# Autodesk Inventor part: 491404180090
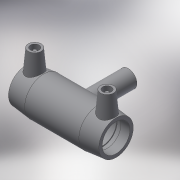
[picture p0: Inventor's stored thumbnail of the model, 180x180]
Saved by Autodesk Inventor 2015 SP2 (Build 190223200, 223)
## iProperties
Created: 2017-06
Part Number: 491404180090
Material: Generic
Description: PLASSON REDUCING TEE 180x90x180
Document SubType Name: Modeling
Designer: KIM
Mass: 57.3761 g
Surface Area: 241.06 cm^2
Volume: 57.3761 cm^3
Density: 1 g/cm^3
Appearance: Default
Author: KIM
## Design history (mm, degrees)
derived "491404.ipt"
feature "Solid1::491404.ipt"
tag "TaggingFeature1"
body "Solid1"
other parameters: "d0" = 422, "d2" = 245, "d3" = 106, "d4" = 84.4, "d5" = 220.5, "d6" = 171, "d8" = 168 deg, "d10" = 42.4, "d11" = 14.13333, "d13" = 422, "d14" = 17.6296, "d17" = 162, "d19" = 3.52592, "d20" = 168 deg, "d22" = 227.85, "d23" = 245, "d25" = 135 deg, "d26" = 295.4, "d29" = 116, "d30" = 15, "d31" = 168.8, "d34" = 5 deg, "d35" = 15, "d39" = 5 deg, "d41" = 4, "d42" = 14, "d43" = 0, "d45" = 4, "d46" = 6, "d47" = 0, "d51" = 0, "d52" = 72, "d54" = 0, "d55" = 220.5, "d56" = 245, "d57" = 147.7, "d58" = 135 deg, "d59" = 106, "d60" = 106, "d61" = 135 deg, "d72" = 192.01, "d73" = 96.005, "d75" = 94.5, "d77" = 0, "d78" = 72, "d80" = 0, "d82" = 77.5, "d83" = 0, "d84" = 3, "d85" = 0, "d86" = 35.33333, "d87" = 223.293, "d88" = 14.13333, "d89" = 3, "d90" = 0, "L_" = 422, "L_1" = 106, "D_" = 245, "A_" = 116, "d_2" = 12
